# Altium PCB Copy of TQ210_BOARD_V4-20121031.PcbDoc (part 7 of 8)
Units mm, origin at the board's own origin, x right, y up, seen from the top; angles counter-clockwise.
Board outline 191.2 x 131.27 mm, 2 copper layers (TopLayer, BottomLayer); 362 components, 455 nets, 1594 pads, 630 vias.
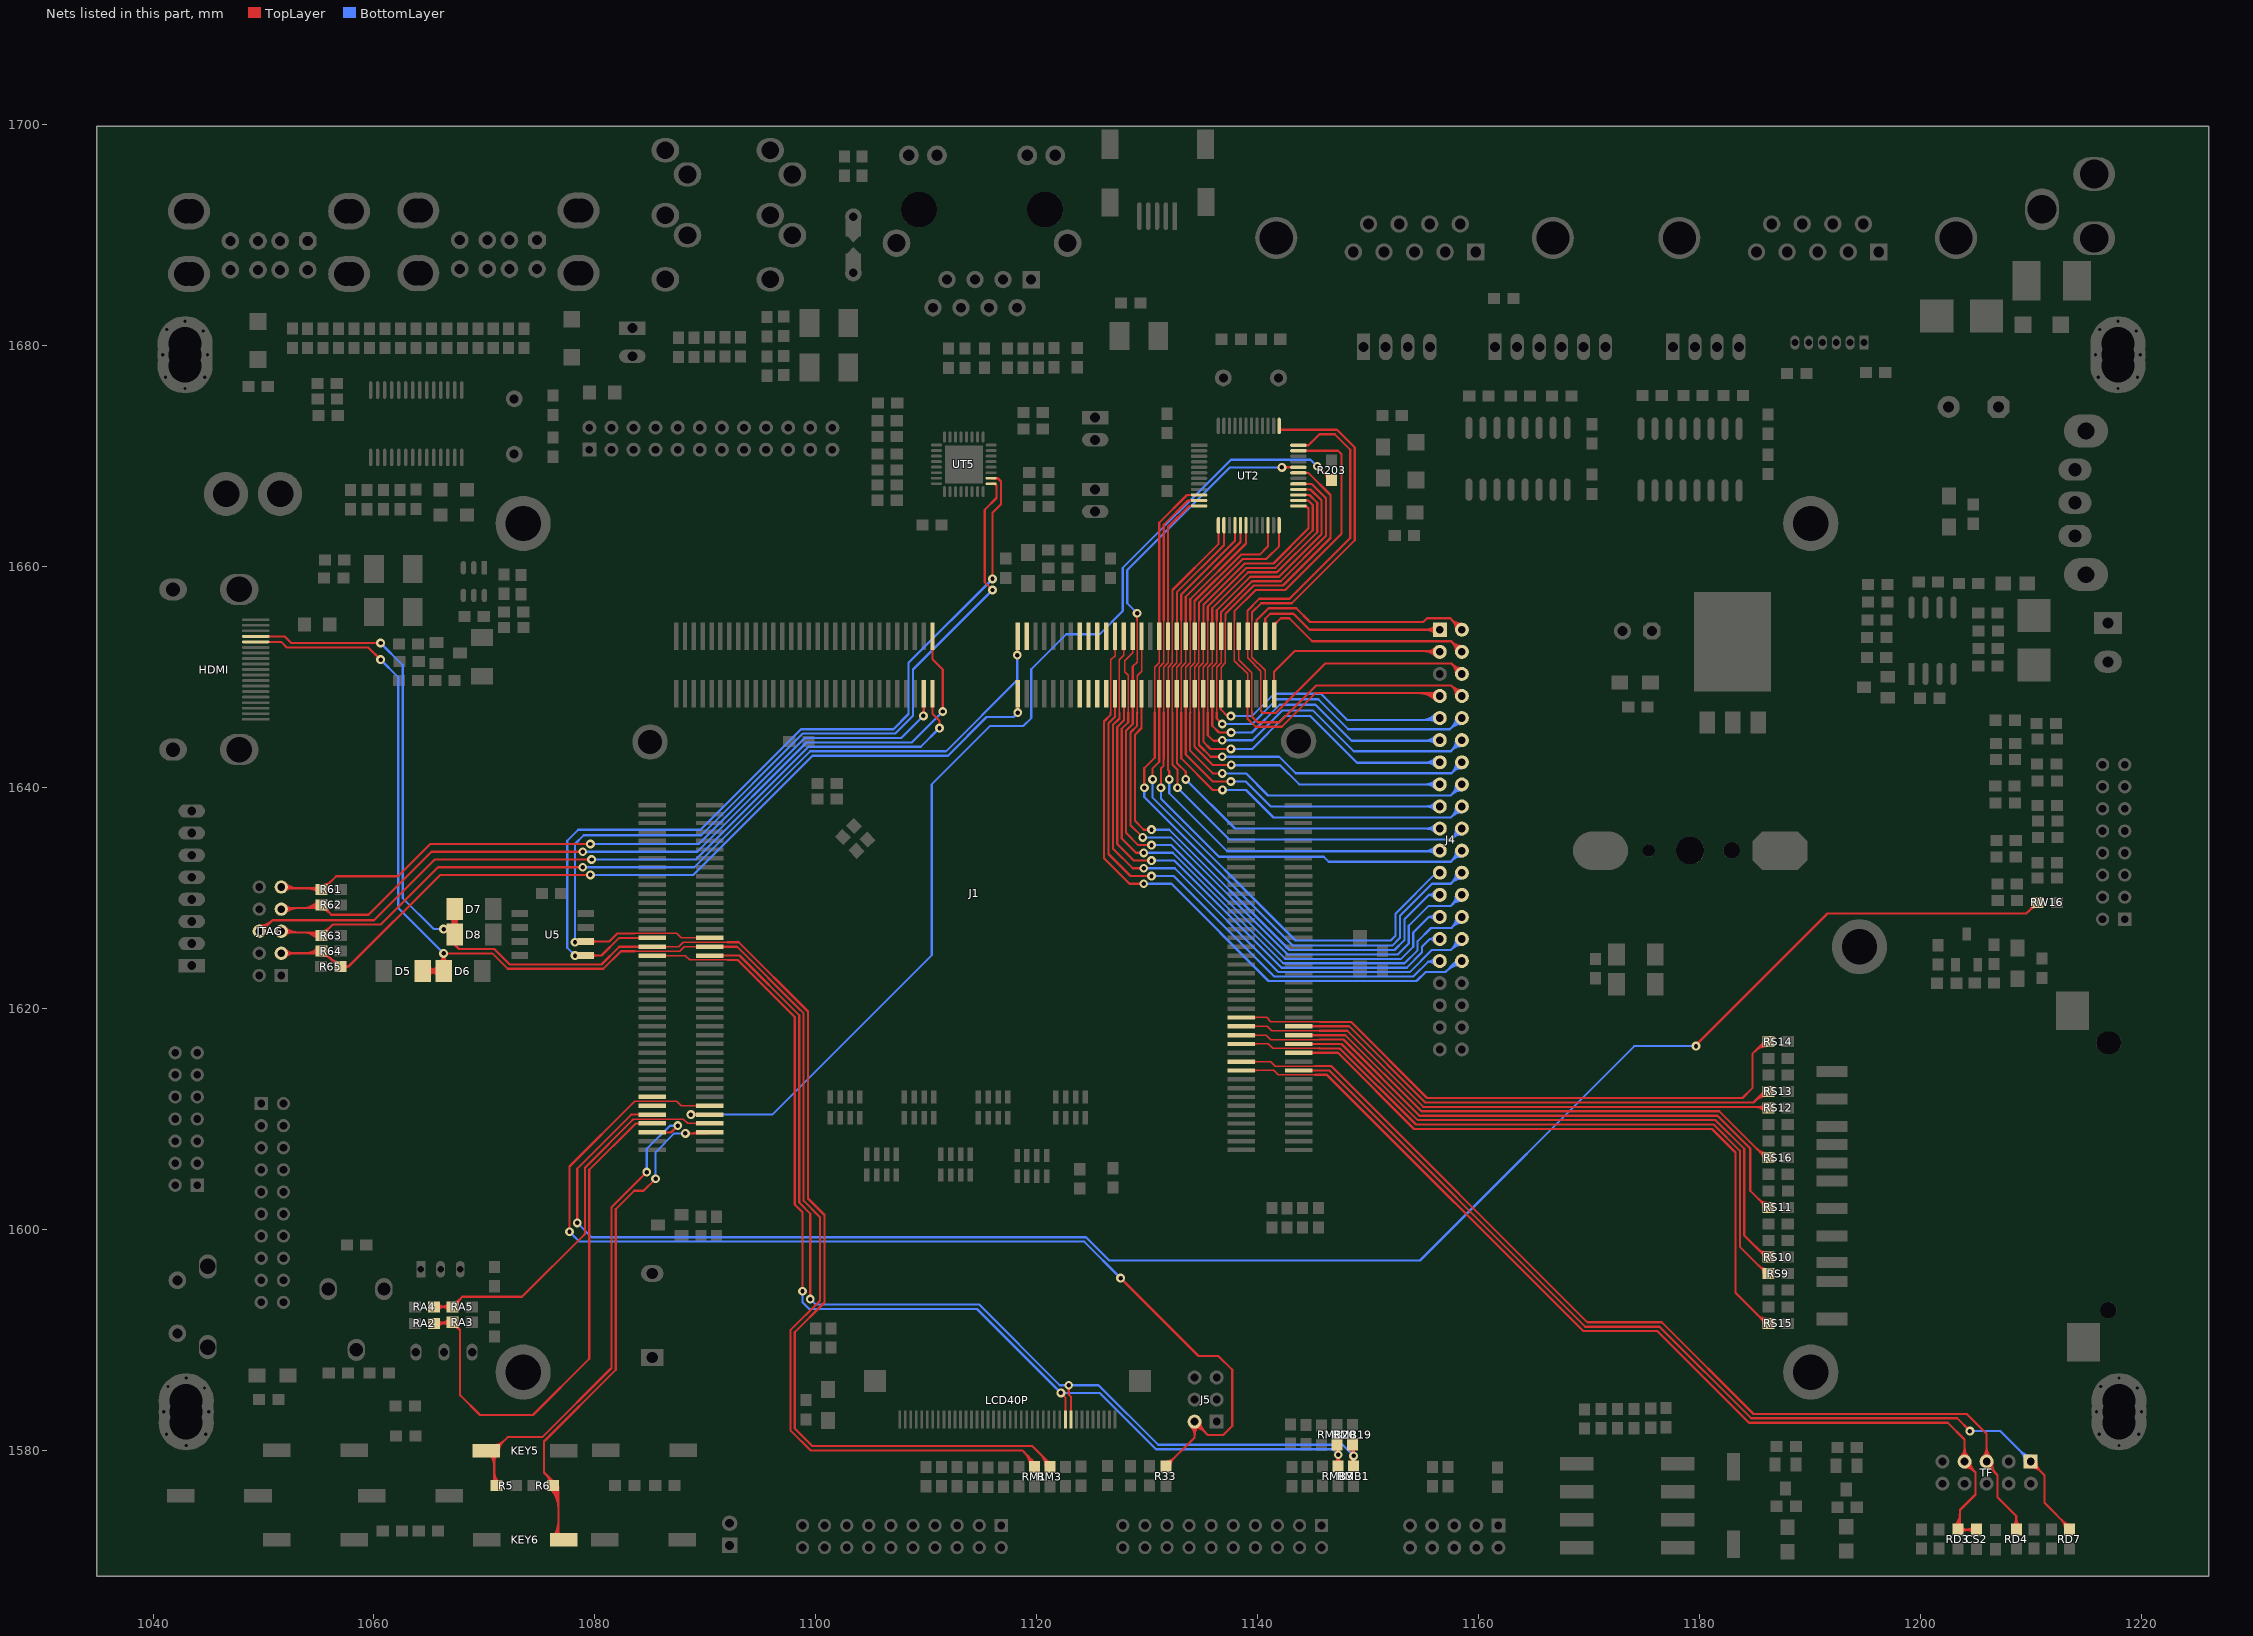
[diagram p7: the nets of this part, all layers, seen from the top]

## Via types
v1: diameter 1, hole 0.5, TopLayer to BottomLayer, 458 vias
v2: diameter 0.8, hole 0.4, TopLayer to BottomLayer, 172 vias

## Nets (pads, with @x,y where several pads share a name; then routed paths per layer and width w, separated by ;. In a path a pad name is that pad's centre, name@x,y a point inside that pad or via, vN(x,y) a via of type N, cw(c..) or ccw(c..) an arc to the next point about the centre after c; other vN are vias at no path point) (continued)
XEINT4: J1.5 KEY5.1 R5.1 | length 52.6
  TopLayer w0.2: KEY5.1@1070.472,1579.622 cw(c1069.44,1578.59) 1070.9,1578.59 ; KEY5.1@1070.614,1579.764 cw(c1069.923,1579.073) 1070.9,1579.073 ; R5.1@1070.767,1577.083 ccw(c1070.446,1577.404) 1070.9,1577.404 ; KEY5.1@1070.826,1580.276 ccw(c1070.826,1581.121) KEY5.1@1071.423,1580.523 ; KEY5.1@1070.826,1580.476 ccw(c1070.826,1581.804) 1071.765,1580.865 ; R5.1@1070.9,1576.8 1070.9,1580 1072.1,1581.2 1075.234,1581.2 1081.5,1587.466 1081.5,1602 v2(1084.7,1605.2) ; 1070.9,1577.645 ccw(c1071.895,1577.645) R5.1@1071.191,1576.941 ; 1070.9,1578.128 ccw(c1072.378,1578.128) R5.1@1071.333,1577.083 ; 1070.9,1578.948 cw(c1071.854,1578.948) KEY5.1@1071.18,1579.622 ; KEY5.1@1071.126,1579.976 cw(c1071.73,1579.976) KEY5.1@1071.303,1580.403 ; KEY5.1@1071.326,1579.976 cw(c1072.412,1579.976) 1071.644,1580.744 ; J1.5@1085.21,1608.79 1086.89,1608.79 v2(1087.5,1609.4) ; J1.5@1086.321,1608.729 cw(c1086.466,1608.584) 1086.466,1608.79 ; J1.5@1086.321,1608.871 ccw(c1086.517,1609.067) 1086.517,1608.79
  BottomLayer w0.2: v2(1084.7,1605.2) 1084.7,1607.3 1086.8,1609.4 v2(1087.5,1609.4)
XEINT5: J1.6 KEY6.1 R6.1 | length 57.5
  TopLayer w0.2: 1075.509,1577.891 cw(c1074.445,1576.826) R6.1@1075.95,1576.803 ; 1075.843,1577.557 cw(c1075.103,1576.816) R6.1@1076.15,1576.8 ; R6.1@1075.967,1576.517 cw(c1074.198,1574.748) 1076.7,1574.748 ; R6.1@1076.109,1576.659 cw(c1074.681,1575.231) 1076.7,1575.231 ; KEY6.1@1076.196,1572.254 ccw(c1074.981,1573.469) 1076.7,1573.469 ; R6.1@1076.25,1576.8 cw(c1075.164,1575.714) 1076.7,1575.714 ; KEY6.1@1076.338,1572.112 ccw(c1075.464,1572.986) 1076.7,1572.986 ; R6.1@1076.391,1576.941 cw(c1075.646,1576.196) 1076.7,1576.196 ; KEY6.1@1076.479,1571.971 ccw(c1075.946,1572.504) 1076.7,1572.504 ; KEY6.1@1076.7,1571.9 1076.7,1576.7 1075.4,1578 1075.4,1580.8 1081.9,1587.3 1081.9,1601.834 1083.566,1603.5 1084.4,1603.5 v2(1085.5,1604.6) ; 1076.7,1572.745 ccw(c1077.395,1572.745) KEY6.1@1076.904,1572.254 ; v2(1088.2,1608.7) 1090.321,1608.7 J1.6@1090.41,1608.79 ; 1088.867,1608.7 ccw(c1088.867,1609.283) J1.6@1089.279,1608.871
  BottomLayer w0.2: v2(1085.5,1604.6) 1085.5,1607 1087.2,1608.7 v2(1088.2,1608.7)
XEINT6: J1.7 RA2.2 RA3.1 | length 52.6
  TopLayer w0.2: RA2.2@1065.45,1591.5 1067.2,1591.5 1067.8,1590.9 1067.8,1585 1069.6,1583.2 1074.406,1583.2 1079.5,1588.294 1079.5,1591.2 1079.5,1605.4 1083.69,1609.59 J1.7@1085.21,1609.59 ; RA2.2@1065.783,1591.217 cw(c1066.466,1590.534) 1066.466,1591.5 cw(c1066.466,1592.466) RA2.2@1065.783,1591.783 ; RA2.2@1065.843,1591.5 ccw(c1065.843,1592.807) RA3.1@1066.767,1591.883 ; RA3.1@1066.767,1591.317 ccw(c1066.326,1590.876) 1066.326,1591.5 ccw(c1066.326,1592.324) RA3.1@1066.909,1591.741 ; RA3.1@1067.15,1591.2 cw(c1067.15,1590.355) 1067.747,1590.953 ; RA3.1@1067.548,1591.56 ccw(c1068.332,1591.482) 1067.775,1590.925
XEINT7: J1.257 RS15.2 | length 62.3
  TopLayer w0.2: J1.257@1143.715,1615.995 1147.276,1615.995 1154.171,1609.1 1181.137,1609.1 1183.269,1606.969 1183.269,1594.259 1186.028,1591.5 RS15.2@1186.25,1591.5 ; 1185.223,1592.305 ccw(c1186.2,1593.282) RS15.2@1186.2,1591.9 ; 1185.564,1591.963 ccw(c1186.2,1592.599) RS15.2@1186.2,1591.7 ; 1185.639,1591.889 cw(c1185.25,1591.5) RS15.2@1185.8,1591.5
XEINT8: J1.8 RA4.2 RA5.1 | length 41
  TopLayer w0.135: 1083.5,1610 1088,1610 1088.4,1609.6 J1.8@1090.4,1609.6 ; J1.8@1089.256,1609.506 ccw(c1089.03,1609.28) 1089.03,1609.6 ccw(c1089.03,1609.92) J1.8@1089.256,1609.694
  TopLayer w0.2: RA4.2@1065.45,1593 RA5.1@1067.1,1593 1068,1593.9 1073.4,1593.9 1079.032,1599.532 ; RA4.2@1065.783,1592.717 cw(c1066.466,1592.034) 1066.466,1593 cw(c1066.466,1593.966) RA4.2@1065.783,1593.283 ; RA5.1@1066.767,1592.717 ccw(c1066.084,1592.034) 1066.084,1593 ccw(c1066.084,1593.966) RA5.1@1066.767,1593.283 ; RA5.1@1067.15,1593.4 ccw(c1067.15,1594.245) 1067.747,1593.647 ; RA5.1@1067.35,1593 cw(c1067.954,1593) RA5.1@1067.527,1593.427 ; RA5.1@1067.55,1593 cw(c1068.636,1593) 1067.868,1593.768 ; 1079.1,1599.6 1079.1,1605.6 1083.426,1609.926
XEINT9: J1.9 RW16.1 | length 162.8
  TopLayer w0.2: v2(1078.4,1600.6) 1078.4,1605.5 1083.3,1610.4 J1.9@1085.2,1610.4 J1.9@1085.21,1610.39 ; v2(1179.7,1616.6) 1179.7,1616.7 1191.6,1628.6 1209.6,1628.6 1210.605,1629.605 RW16.1@1210.621,1629.605 ; 1209.865,1628.865 ccw(c1209.125,1629.605) RW16.1@1210.171,1629.605 ; 1209.946,1628.946 cw(c1210.571,1628.32) RW16.1@1210.571,1629.205 ; RW16.1@1210.206,1629.206 ccw(c1209.808,1629.605) RW16.1@1210.371,1629.605
  BottomLayer w0.2: v2(1078.4,1600.6) 1079.7,1599.3 1124.466,1599.3 1126.566,1597.2 1154.7,1597.2 1174.1,1616.6 v2(1179.7,1616.6)
XEINT10: J1.10 R203.2 | length 101.6
  TopLayer w0.2: v2(1088.7,1610.4) J1.10@1090.4,1610.4 J1.10@1090.41,1610.39 ; J1.10@1089.279,1610.329 ccw(c1089.109,1610.159) 1089.109,1610.4 ccw(c1089.109,1610.641) J1.10@1089.279,1610.471 ; v2(1145.4,1669.1) 1145.45,1669.1 R203.2@1146.7,1667.85 R203.2@1146.5,1667.85 ; 1145.932,1668.618 ccw(c1146.7,1669.386) R203.2@1146.7,1668.3 ; 1146.053,1668.497 cw(c1145.455,1667.9) R203.2@1146.3,1667.9 ; R203.2@1146.273,1668.277 ccw(c1146.7,1668.704) R203.2@1146.7,1668.1
  BottomLayer w0.2: v2(1088.7,1610.4) 1096.059,1610.4 1110.5,1624.84 1110.5,1640.299 1115.798,1645.597 1118.805,1645.597 1119.505,1646.297 1119.505,1650.734 1122.671,1653.9 1125.7,1653.9 1127.8,1656 1127.8,1659.9 1137.6,1669.7 1144.8,1669.7 v2(1145.4,1669.1)
XEINT11: J1.11
XEINT14: J1.12 J5.2 R33.2 | length 113.2
  TopLayer w0.135: 1083.6,1611.6 1087.4,1611.6 1087.8,1611.2 J1.12@1090.4,1611.2 ; J1.12@1089.256,1611.106 ccw(c1089.03,1610.88) 1089.03,1611.2 ccw(c1089.03,1611.52) J1.12@1089.256,1611.294
  TopLayer w0.2: v2(1077.7,1599.8) 1077.7,1605.7 1083.6,1611.6 ; v2(1127.6,1595.6) 1134.652,1588.548 1136.452,1588.548 1137.7,1587.3 1137.7,1582.2 1136.9,1581.4 1135.5,1581.4 J5.2@1134.3,1582.6 1134.3,1581.15 R33.2@1131.7,1578.55 ; R33.2@1131.7,1578.8 ccw(c1131.7,1579.404) R33.2@1132.127,1578.977 ; R33.2@1131.7,1579 ccw(c1131.7,1580.086) 1132.468,1579.318 ; R33.2@1132.1,1578.6 cw(c1132.945,1578.6) 1132.347,1579.197 ; J5.2@1133.922,1582.222 cw(c1133.008,1581.308) 1134.3,1581.308 cw(c1135.592,1581.308) J5.2@1134.678,1582.222 ; J5.2@1134.063,1582.363 cw(c1133.491,1581.791) 1134.3,1581.791 cw(c1135.109,1581.791) J5.2@1134.537,1582.363 ; 1134.872,1582.028 cw(c1135.444,1582.6) 1134.635,1582.6 ccw(c1135.444,1582.6) 1134.872,1582.028 ; 1134.872,1582.028 ccw(c1134.3,1581.456) 1134.3,1582.265 cw(c1134.3,1581.456) 1134.872,1582.028 ; 1135.213,1581.687 cw(c1136.127,1582.6) 1134.835,1582.6 ccw(c1136.127,1582.6) 1135.213,1581.687 ; 1135.213,1581.687 ccw(c1134.3,1580.773) 1134.3,1582.065 cw(c1134.3,1580.773) 1135.213,1581.687
  BottomLayer w0.2: v2(1077.7,1599.8) 1078.6,1598.9 1124.3,1598.9 v2(1127.6,1595.6)
XEINT15: J1.13
XI2CSCL0: J1.50 U5.6 UT5.17 | length 82.7
  TopLayer w0.135: 1083.6,1626.8 1087.4,1626.8 1087.8,1626.4 J1.50@1090.4,1626.4
  TopLayer w0.2: U5.6@1079.194,1626.072 1081.306,1626.072 1082.034,1626.8 1083.6,1626.8 ; U5.6@1079.78,1625.918 cw(c1080.151,1625.547) 1080.151,1626.072 cw(c1080.151,1626.597) U5.6@1079.78,1626.226 ; UT5.17@1115.878,1667.524 1116.176,1667.524 1116.368,1667.332 1116.368,1666.234 1115.3,1665.166 1115.3,1658.6 v2(1116,1657.9) ; UT5.17@1116.235,1667.506 cw(c1115.914,1667.185) 1116.368,1667.185 ; UT5.17@1116.242,1667.502 cw(c1116.144,1667.3) 1116.368,1667.3 ; UT5.17@1116.278,1667.521 ccw(c1116.459,1667.499) 1116.33,1667.37
  BottomLayer w0.2: v2(1078.2,1626) 1078.2,1634.9 1079,1635.7 1089.634,1635.7 1098.834,1644.9 1107.2,1644.9 1108.8,1646.5 1108.8,1650.7 v2(1116,1657.9)
XI2CSCL1: D5.1 D6.2 HDMI.15 J1.48 RM1.2 | length 158.7
  TopLayer w0.12: 1083.6,1625.2 1087.2,1625.2 1087.7,1625.2 1088.09,1625.59 J1.48@1090.41,1625.59
  TopLayer w0.2: HDMI.15@1049.3,1653.2 1051.6,1653.2 1052.1,1652.7 1059.495,1652.7 v2(1060.598,1651.597) ; D5.1@1064.4,1623.4 D6.2@1066.3,1623.4 v2(1066.3,1625) ; D5.1@1064.718,1623.082 cw(c1065.486,1622.314) 1065.486,1623.4 cw(c1065.486,1624.486) D5.1@1064.718,1623.718 ; D5.1@1064.86,1622.94 cw(c1065.969,1621.831) 1065.969,1623.4 cw(c1065.969,1624.969) D5.1@1064.86,1623.86 ; D6.2@1065.84,1622.94 ccw(c1064.731,1621.831) 1064.731,1623.4 ccw(c1064.731,1624.969) D6.2@1065.84,1623.86 ; D6.2@1065.895,1624.158 ccw(c1065.223,1625) v2(1066.3,1625) ; D6.2@1065.982,1623.082 ccw(c1065.214,1622.314) 1065.214,1623.4 ccw(c1065.214,1624.486) D6.2@1065.982,1623.718 ; D6.2@1066.019,1624.002 ccw(c1065.555,1624.585) 1066.3,1624.585 ccw(c1067.045,1624.585) D6.2@1066.581,1624.002 ; D6.2@1066.705,1624.158 cw(c1067.377,1625) v2(1066.3,1625) ; 1083.6,1625.2 1082.367,1625.2 1080.767,1623.6 1072.1,1623.6 1070.7,1625 v2(1066.3,1625) ; J1.48@1090.41,1625.59 1092.879,1625.59 1098.4,1620.068 1098.9,1619.569 1098.9,1602.6 1100.39,1601.11 1100.39,1593.556 1097.7,1590.866 1097.7,1581.82 1099.52,1580 1118.7,1580 RM1.2@1120,1578.7 ; 1118.868,1579.832 cw(c1117.585,1578.548) RM1.2@1119.4,1578.548 ; 1119.21,1579.49 cw(c1118.268,1578.548) RM1.2@1119.6,1578.548 ; 1119.551,1579.149 cw(c1118.951,1578.548) RM1.2@1119.8,1578.548
  BottomLayer w0.2: v2(1060.598,1651.597) 1062.2,1649.995 1062.2,1629.1 v2(1066.3,1625)
XI2CSCL2: J1.46 LCD40P.32 RMB1.2 RMB19.2 | length 100.1
  TopLayer w0.2: J1.46@1090.41,1624.79 1090.421,1624.8 1093.103,1624.8 1098.5,1619.403 1098.5,1602.434 1099.5,1601.434 v2(1099.5,1593.7) ; v2(1122.9,1585.9) 1122.9,1585.066 1123.1,1584.866 LCD40P.32@1123.1,1582.8 ; RMB19.2@1148.317,1580.217 cw(c1147.393,1579.293) v2@1148.7,1579.293 ; RMB1.2@1148.417,1578.883 ccw(c1147.734,1579.566) 1148.7,1579.566 ccw(c1149.666,1579.566) RMB1.2@1148.983,1578.883 ; RMB19.2@1148.459,1580.359 cw(c1147.876,1579.776) 1148.7,1579.776 cw(c1149.324,1579.776) RMB19.2@1148.883,1580.217 ; RMB1.2@1148.7,1578.55 RMB19.2@1148.7,1580.25
  BottomLayer w0.2: v2(1099.5,1593.7) 1100,1593.2 1114.8,1593.2 1122.1,1585.9 1125.6,1585.9 1131,1580.5 1147.7,1580.5 v2(1148.7,1579.5)
XI2CSDA0: J1.49 U5.5 UT5.18 | length 80.2
  TopLayer w0.2: U5.5@1079.194,1624.802 1080.602,1624.802 1082.2,1626.4 J1.49@1085.2,1626.4 ; U5.5@1079.78,1624.648 cw(c1080.151,1624.277) 1080.151,1624.802 cw(c1080.151,1625.327) U5.5@1079.78,1624.956 ; UT5.18@1115.878,1668.024 1116.471,1668.024 1116.768,1667.726 1116.768,1665.668 1116,1664.9 v2(1116,1658.9) ; UT5.18@1116.253,1667.999 cw(c1116.253,1667.413) 1116.667,1667.827 ; UT5.18@1116.259,1668 cw(c1116.347,1667.682) 1116.579,1667.915
  BottomLayer w0.2: v2(1078.2,1624.8) 1077.5,1625.5 1077.5,1635.2 1078.5,1636.2 1089.569,1636.2 1098.669,1645.3 1107.034,1645.3 1108.4,1646.666 1108.4,1651.3 v2(1116,1658.9)
XI2CSDA1: D7.1 D8.2 HDMI.16 J1.47 RM3.2 | length 154.9
  TopLayer w0.135: J1.47@1085.2,1625.6 1087.6,1625.6 1088,1626 1092,1626
  TopLayer w0.2: HDMI.16@1049.3,1653.7 1051.9,1653.7 1052.503,1653.097 v2(1060.598,1653.097) ; D8.2@1066.84,1627.41 ccw(c1065.731,1628.519) 1067.3,1628.519 ccw(c1068.869,1628.519) D8.2@1067.76,1627.41 ; D7.1@1066.84,1628.29 cw(c1065.731,1627.181) 1067.3,1627.181 cw(c1068.869,1627.181) D7.1@1067.76,1628.29 ; D8.2@1066.982,1627.268 ccw(c1066.214,1628.036) 1067.3,1628.036 ccw(c1068.386,1628.036) D8.2@1067.618,1627.268 ; D7.1@1066.982,1628.432 cw(c1066.214,1627.664) 1067.3,1627.664 cw(c1068.386,1627.664) D7.1@1067.618,1628.432 ; D7.1@1067.3,1629.4 1067.3,1625.8 1067.7,1625.4 1070.9,1625.4 1072.3,1624 1080.601,1624 1082.201,1625.6 J1.47@1085.2,1625.6 J1.47@1085.21,1625.59 ; 1092,1626 1093.034,1626 1099.3,1619.734 1099.3,1602.8 1100.79,1601.31 1100.79,1593.39 1098.1,1590.7 1098.1,1581.985 1099.685,1580.4 1119.6,1580.4 RM3.2@1121.3,1578.7 ; 1120.339,1579.661 cw(c1119.226,1578.548) RM3.2@1120.8,1578.548 ; 1120.681,1579.319 cw(c1119.909,1578.548) RM3.2@1121,1578.548 ; 1120.947,1579.053 ccw(c1121.2,1579.306) RM3.2@1121.2,1578.948
  BottomLayer w0.2: v2(1060.598,1653.097) 1062.6,1651.095 1062.6,1630 1065.4,1627.2 v2(1066.3,1627.2)
XI2CSDA2: J1.45 LCD40P.31 RMB3.2 RMB20.2 | length 103.5
  TopLayer w0.135: J1.45@1085.2,1624.8 1088.2,1624.8 1088.6,1624.4 1092,1624.4
  TopLayer w0.2: 1092,1624.4 1092.937,1624.4 1098.1,1619.237 1098.1,1602.269 1098.8,1601.569 v2(1098.8,1594.4) ; v2(1122.2,1585.2) 1122.6,1584.8 LCD40P.31@1122.6,1582.8 ; RMB20.2@1146.917,1580.217 cw(c1145.993,1579.293) v2@1147.3,1579.293 ; RMB3.2@1147.017,1578.883 ccw(c1146.334,1579.566) 1147.3,1579.566 ccw(c1148.266,1579.566) RMB3.2@1147.583,1578.883 ; RMB20.2@1147.059,1580.359 cw(c1146.476,1579.776) 1147.3,1579.776 cw(c1147.924,1579.776) RMB20.2@1147.483,1580.217 ; RMB3.2@1147.3,1578.55 RMB20.2@1147.3,1580.25
  BottomLayer w0.2: v2(1098.8,1594.4) 1098.8,1593.4 1099.4,1592.8 1114.6,1592.8 v2(1122.2,1585.2) 1125.7,1585.2 1130.8,1580.1 1146.8,1580.1 v2(1147.3,1579.6)
XJDBGSEL: J1.143
XJTCK: J1.138 JTAG.9 R61.2 | length 73.9
  TopLayer w0.2: JTAG.9@1051.712,1630.904 1055.504,1630.904 1056.585,1631.985 1062.185,1631.985 1065.1,1634.9 v2(1079.6,1634.9) ; JTAG.9@1051.824,1631.216 ccw(c1052.578,1631.969) 1052.578,1630.904 ccw(c1052.578,1630.038) JTAG.9@1051.966,1630.65 ; JTAG.9@1051.966,1631.357 ccw(c1053.061,1632.452) 1053.061,1630.904 ; 1053.968,1630.904 cw(c1053.968,1629.577) R61.2@1054.906,1630.515 ; 1054.451,1630.904 cw(c1054.451,1630.06) R61.2@1055.048,1630.656 ; 1054.479,1630.904 ccw(c1054.479,1631.508) R61.2@1054.906,1631.081 ; R61.2@1055.289,1630.998 ccw(c1055.289,1631.743) 1055.816,1631.216 ; R61.2@1055.289,1631.198 ccw(c1055.289,1632.426) 1056.158,1631.558 ; R61.2@1055.689,1630.798 cw(c1056.392,1630.798) 1055.895,1631.295 ; J1.138@1109.7,1647.385 cw(c1109.529,1647.214) 1109.771,1647.214 cw(c1110.012,1647.214) J1.138@1109.841,1647.385 ; v2@1109.771,1646.521 J1.138@1109.771,1648.506
  BottomLayer w0.2: v2(1079.6,1634.9) 1089.4,1634.9 1099,1644.5 1107.75,1644.5 v2(1109.75,1646.5)
XJTDI: J1.141 JTAG.5 R63.2 | length 88.8
  TopLayer w0.2: JTAG.5@1051.712,1626.904 1051.716,1626.9 R63.2@1055.3,1626.9 ; JTAG.5@1051.824,1627.216 ccw(c1052.586,1627.978) 1052.586,1626.9 ; JTAG.5@1051.966,1626.65 cw(c1052.569,1626.047) 1052.569,1626.9 ; JTAG.5@1051.966,1627.357 ccw(c1053.069,1628.461) 1053.069,1626.9 ; 1053.494,1626.9 cw(c1053.494,1624.903) R63.2@1054.906,1626.315 ; 1053.977,1626.9 cw(c1053.977,1625.386) R63.2@1055.048,1626.456 ; 1054.46,1626.9 cw(c1054.46,1625.869) R63.2@1055.189,1626.598 ; R63.2@1055.239,1626.598 1056.241,1627.6 1060.6,1627.6 1065.8,1632.8 v2(1078.9,1632.8) ; R63.2@1055.289,1626.998 ccw(c1055.289,1627.843) 1055.887,1627.245 ; R63.2@1055.489,1626.598 cw(c1056.093,1626.598) R63.2@1055.666,1627.025 ; R63.2@1055.689,1626.598 cw(c1056.776,1626.598) 1056.007,1627.366 ; v2(1118.25,1652) J1.141@1118.25,1653.5 ; v2@1118.25,1652.304 cw(c1118.647,1652.304) J1.141@1118.366,1652.585 ; J1.141@1118.296,1653.5 J1.141@1118.296,1653.706
  BottomLayer w0.2: v2(1078.9,1632.8) 1089.001,1632.8 1099.501,1643.3 1111.804,1643.3 1118.25,1649.746 v2(1118.25,1652)
XJTDO: J1.140 JTAG.6 | length 75.7
  TopLayer w0.2: JTAG.6@1049.612,1627.304 ccw(c1049.612,1628.511) 1050.466,1627.657 ; JTAG.6@1049.612,1627.504 ccw(c1049.612,1629.194) 1050.807,1627.999 ; JTAG.6@1049.712,1626.904 1050.808,1628 1060,1628 1065.5,1633.5 v2(1079.7,1633.5) ; JTAG.6@1050.112,1627.004 cw(c1050.836,1627.004) 1050.324,1627.516 ; J1.140@1110.5,1647.385 cw(c1110.329,1647.214) 1110.571,1647.214 cw(c1110.812,1647.214) J1.140@1110.641,1647.385 ; J1.140@1110.571,1648.506 1110.571,1646.7 1111.2,1646.071 v2(1111.2,1645.4)
  BottomLayer w0.2: v2(1079.7,1633.5) 1089.135,1633.5 1099.335,1643.7 1109.5,1643.7 v2(1111.2,1645.4)
XJTMS: J1.139 JTAG.7 R62.2 | length 83.8
  TopLayer w0.2: JTAG.7@1051.6,1629.1 1054.941,1629.1 R62.2@1055.239,1629.398 1056.137,1628.5 1059.5,1628.5 1065.2,1634.2 v2(1078.9,1634.2) ; JTAG.7@1051.824,1628.791 cw(c1052.569,1628.047) 1052.569,1629.1 ; JTAG.7@1051.966,1628.65 cw(c1053.052,1627.564) 1053.052,1629.1 ; JTAG.7@1051.966,1629.357 ccw(c1052.586,1629.978) 1052.586,1629.1 ; 1053.504,1629.1 ccw(c1053.504,1631.083) R62.2@1054.906,1629.681 ; 1053.987,1629.1 ccw(c1053.987,1630.6) R62.2@1055.048,1629.539 ; 1054.47,1629.1 ccw(c1054.47,1630.117) R62.2@1055.189,1629.398 ; R62.2@1055.289,1628.998 cw(c1055.289,1628.153) 1055.887,1628.75 ; R62.2@1055.489,1629.398 ccw(c1056.093,1629.398) R62.2@1055.666,1628.971 ; R62.2@1055.689,1629.398 ccw(c1056.776,1629.398) 1056.007,1628.63 ; J1.139@1110.5,1652.585 cw(c1110.329,1652.414) 1110.571,1652.414 cw(c1110.812,1652.414) J1.139@1110.641,1652.585 ; J1.139@1110.571,1653.706 1110.571,1651.629 1111.5,1650.699 v2(1111.5,1646.9)
  BottomLayer w0.2: v2(1078.9,1634.2) 1089.27,1634.2 1099.17,1644.1 1108.7,1644.1 v2(1111.5,1646.9)
XJTRSTN: J1.142 JTAG.3 R64.2 R65.2 | length 89.4
  TopLayer w0.2: JTAG.3@1051.612,1625.004 1055.596,1625.004 R65.2@1056.6,1624 ; JTAG.3@1051.824,1624.791 cw(c1052.336,1624.279) 1052.336,1625.004 cw(c1052.336,1625.728) JTAG.3@1051.824,1625.216 ; JTAG.3@1051.966,1624.65 cw(c1052.819,1623.796) 1052.819,1625.004 cw(c1052.819,1626.211) JTAG.3@1051.966,1625.357 ; 1053.754,1625.004 ccw(c1053.754,1626.633) R64.2@1054.906,1625.481 ; 1054.237,1625.004 ccw(c1054.237,1626.15) R64.2@1055.048,1625.339 ; R64.2@1054.692,1625.004 cw(c1054.692,1624.701) R64.2@1054.906,1624.915 ; R64.2@1054.72,1625.004 ccw(c1054.72,1625.667) R64.2@1055.189,1625.198 ; R64.2@1055.289,1624.798 cw(c1055.289,1623.559) 1056.165,1624.435 ; R64.2@1055.289,1624.998 cw(c1055.289,1624.242) 1055.823,1624.777 ; R64.2@1055.689,1625.198 ccw(c1056.382,1625.198) 1055.892,1624.708 ; 1056.035,1624.565 ccw(c1056.911,1625.441) R65.2@1056.911,1624.202 ; 1056.308,1624.292 cw(c1055.818,1623.802) R65.2@1056.511,1623.802 ; 1056.377,1624.223 ccw(c1056.911,1624.758) R65.2@1056.911,1624.002 ; R65.2@1056.961,1623.802 1057.702,1623.802 ; R65.2@1057.358,1623.603 cw(c1057.702,1623.405) 1057.702,1623.802 ; R65.2@1057.358,1624.001 ccw(c1057.702,1624.199) 1057.702,1623.802 ; v2(1079.6,1632.1) 1066,1632.1 1057.702,1623.802 ; J1.142@1118.225,1647.385 cw(c1118.054,1647.214) 1118.296,1647.214 cw(c1118.537,1647.214) J1.142@1118.366,1647.385 ; v2(1118.296,1646.796) J1.142@1118.296,1648.506
  BottomLayer w0.2: v2(1079.6,1632.1) 1088.901,1632.1 1099.701,1642.9 1111.97,1642.9 1115.466,1646.397 1117.897,1646.397 v2(1118.296,1646.796)
XM0ADDR0: J1.170 J4.25 | length 48.6
  TopLayer w0.2: J1.170@1129.496,1648.506 1129.496,1645.396 1128.9,1644.8 1128.9,1637 1129.7,1636.2 v2(1130.4,1636.2)
  BottomLayer w0.2: v2(1130.4,1636.2) 1132,1636.2 1142.9,1625.3 1152.4,1625.3 1153.294,1626.194 1153.294,1628.07 1155.523,1630.3 ; J4.25@1156.049,1630.012 ccw(c1155.523,1629.676) 1155.523,1630.3 ; J4.25@1156.049,1630.588 cw(c1155.523,1630.924) 1155.523,1630.3 ; J4.25@1156.5,1630.3 1155.523,1630.3
XM0ADDR1: J1.169 J4.26 | length 58.8
  TopLayer w0.135: 1129.094,1646.797 1129.094,1650.14 1129.496,1650.541 J1.169@1129.496,1653.706
  TopLayer w0.2: 1129.1,1646.8 1129.096,1646.796 1129.096,1645.6 1128.5,1645.004 1128.5,1636.6 v2(1129.6,1635.5)
  BottomLayer w0.2: v2(1129.6,1635.5) 1132.134,1635.5 1142.734,1624.9 1152.7,1624.9 1153.694,1625.894 1153.694,1627.494 1155.5,1629.3 1157.5,1629.3 J4.26@1158.5,1630.3 ; J4.26@1157.965,1630.3 cw(c1156.673,1630.3) 1157.587,1629.387 cw(c1158.5,1628.473) J4.26@1158.5,1629.765 ; J4.26@1158.165,1630.3 cw(c1157.356,1630.3) 1157.928,1629.728 cw(c1158.5,1629.156) J4.26@1158.5,1629.965
XM0ADDR2: J1.168 J4.27 UT2.32 | length 80.6
  TopLayer w0.135: 1128.696,1650.979 1129.095,1651.378 1129.095,1655.205
  TopLayer w0.2: 1128.696,1650.979 1128.696,1645.767 1128.1,1645.172 1128.1,1635.9 1129.2,1634.8 v2(1130.4,1634.8) ; 1129.095,1655.205 v2@1129.095,1655.695 ; v2(1142.2,1669) 1142.204,1669.004 UT2.32@1143.703,1669.004
  BottomLayer w0.2: v2(1129.1,1655.8) 1128.2,1656.7 1128.2,1659.7 1137.5,1669 v2(1142.2,1669) ; v2(1130.4,1634.8) 1132.2,1634.8 1142.5,1624.5 1153,1624.5 1154.094,1625.594 1154.094,1626.894 1155.5,1628.3 ; J4.27@1156.055,1628.003 ccw(c1155.5,1627.633) 1155.5,1628.3 ; J4.27@1156.055,1628.597 cw(c1155.5,1628.967) 1155.5,1628.3 ; J4.27@1156.5,1628.3 1155.5,1628.3
XM0ADDR3: J1.167 J4.28 | length 59.9
  TopLayer w0.135: 1128.296,1646.804 1128.296,1650.185 1127.963,1650.517 1127.963,1651.492 1128.696,1652.224 J1.167@1128.696,1653.706
  TopLayer w0.2: 1128.296,1645.933 1127.7,1645.337 1127.7,1635.4 1129,1634.1 v2(1129.7,1634.1) ; 1128.3,1645.933 1128.3,1646.8
  BottomLayer w0.2: v2(1129.7,1634.1) 1132.334,1634.1 1142.334,1624.1 1153.3,1624.1 1154.494,1625.294 1154.494,1626.094 1155.7,1627.3 1157.55,1627.3 J4.28@1158.5,1628.25 ; 1157.575,1627.325 ccw(c1156.633,1628.267) J4.28@1157.965,1628.291 ; 1157.672,1627.422 cw(c1158.5,1626.594) J4.28@1158.5,1627.765 ; 1157.908,1627.658 ccw(c1157.288,1628.279) J4.28@1158.165,1628.294 ; 1158.013,1627.763 cw(c1158.5,1627.277) J4.28@1158.5,1627.965
XM0ADDR4: J1.166 J4.29 | length 50.1
  TopLayer w0.2: J1.166@1127.906,1648.495 1127.906,1646.109 1127.3,1645.503 1127.3,1634.9 1128.8,1633.4 v2(1130.4,1633.4)
  BottomLayer w0.2: v2(1130.4,1633.4) 1132.469,1633.4 1142.169,1623.7 1153.5,1623.7 1154.894,1625.094 1154.894,1625.595 1155.598,1626.3 ; J4.29@1156.03,1626.044 ccw(c1155.598,1625.808) 1155.598,1626.3 ; J4.29@1156.03,1626.556 cw(c1155.598,1626.792) 1155.598,1626.3 ; J4.29@1156.5,1626.3 1155.598,1626.3
XM0ADDR5: J1.165 J4.30 | length 60.9
  TopLayer w0.135: 1127.497,1646.803 1127.497,1651.592 1127.896,1651.991 J1.165@1127.896,1653.706 ; J1.165@1127.802,1652.562 cw(c1127.576,1652.336) 1127.896,1652.336 cw(c1128.215,1652.336) J1.165@1127.989,1652.562
  TopLayer w0.2: 1127.496,1646.264 1126.9,1645.669 1126.9,1634.5 1128.7,1632.7 v2(1129.7,1632.7) ; 1127.5,1646.264 1127.5,1646.8
  BottomLayer w0.2: v2(1129.7,1632.7) 1132.5,1632.7 1141.9,1623.3 1153.778,1623.3 1155.778,1625.3 1157.5,1625.3 J4.30@1158.5,1626.3 ; J4.30@1157.965,1626.3 cw(c1156.673,1626.3) 1157.587,1625.387 cw(c1158.5,1624.473) J4.30@1158.5,1625.765 ; J4.30@1158.165,1626.3 cw(c1157.356,1626.3) 1157.928,1625.728 cw(c1158.5,1625.156) J4.30@1158.5,1625.965
XM0ADDR6: J1.164 J4.31 | length 51.8
  TopLayer w0.2: J1.164@1127.096,1648.506 1127.096,1646.43 1126.5,1645.834 1126.5,1634 1128.5,1632 v2(1130.4,1632)
  BottomLayer w0.2: v2(1130.4,1632) 1132.4,1632 1141.027,1623.373 1141.5,1622.9 1154.1,1622.9 1155.45,1624.25 ; 1155.809,1624.25 ccw(c1155.809,1624.728) J4.31@1156.215,1624.476 ; J4.31@1156.045,1624.582 cw(c1155.45,1624.95) 1155.45,1624.25 ; J4.31@1156.093,1623.953 ccw(c1155.45,1623.406) 1155.45,1624.25 ; J4.31@1156.5,1624.25 1155.45,1624.25
XM0ADDR7: J1.163 J4.32 | length 62.3
  TopLayer w0.135: 1126.695,1646.796 1126.695,1651.565 1127.096,1651.965 J1.163@1127.096,1653.706 ; J1.163@1127.002,1652.562 cw(c1126.776,1652.336) 1127.096,1652.336 cw(c1127.415,1652.336) J1.163@1127.189,1652.562
  TopLayer w0.2: 1126.696,1646.796 1126.696,1646.596 1126.1,1646 1126.1,1633.6 1128.4,1631.3 v2(1129.7,1631.3)
  BottomLayer w0.2: v2(1129.7,1631.3) 1132.2,1631.3 1141,1622.5 1154.4,1622.5 1155.2,1623.3 1157,1623.3 1158,1624.3 J4.32@1158.5,1624.3 ; 1157.088,1623.388 cw(c1158.482,1621.994) J4.32@1158.497,1623.965 ; 1157.425,1623.725 cw(c1158.487,1622.664) J4.32@1158.499,1624.165 ; 1157.763,1624.063 cw(c1158.492,1623.333) J4.32@1158.501,1624.365
XM0ADDR8: J1.162
XM0ADDR9: J1.161
XM0ADDR10: J1.160
XM0ADDR11: J1.159
XM0ADDR12: J1.158
XM0ADDR13: J1.157
XM0ADDR14: J1.156
XM0ADDR15: J1.155
XM0BE0: J1.189
XM0BE1: J1.190
XM0CSN0: J1.195 J4.2 | length 25
  TopLayer w0.2: J1.195@1139.896,1653.706 J1.195@1139.952,1653.762 ; J1.195@1139.9,1653.71 1139.9,1655.164 1140.986,1656.25 1143.5,1656.25 1144.75,1655 1155,1655 1155.35,1655.35 1157.45,1655.35 J4.2@1158.5,1654.3 ; J4.2@1157.965,1654.3 ccw(c1156.673,1654.3) 1157.587,1655.213 ccw(c1158.5,1656.127) J4.2@1158.5,1654.835 ; J4.2@1158.165,1654.3 ccw(c1157.356,1654.3) 1157.928,1654.872 ccw(c1158.5,1655.444) J4.2@1158.5,1654.635
XM0CSN1: J1.198 UT2.37 | length 35.8
  TopLayer w0.12: J1.198@1140.696,1648.506 J1.198@1140.696,1648.508
  TopLayer w0.135: 1139.497,1655.197 1139.497,1651.817 1140.696,1650.619 J1.198@1140.696,1648.506
  TopLayer w0.2: 1139.5,1655.2 1139.5,1655.877 ; 1139.54,1655.917 1140.323,1656.7 1143.1,1656.7 1148.8,1662.4 1148.8,1670.8 1147.2,1672.4 UT2.37@1141.903,1672.4
XM0CSN3: J1.197 J4.1 | length 21.9
  TopLayer w0.2: J1.197@1140.625,1654.827 ccw(c1140.454,1654.997) 1140.696,1654.997 ccw(c1140.937,1654.997) J1.197@1140.766,1654.827 ; J1.197@1140.696,1653.706 1140.696,1655.293 1141.153,1655.75 1143.25,1655.75 1144.7,1654.3 J4.1@1156.5,1654.3 ; J4.1@1156.122,1653.922 ccw(c1155.208,1653.008) 1155.208,1654.3 ccw(c1155.208,1655.592) J4.1@1156.122,1654.678 ; J4.1@1156.263,1654.063 ccw(c1155.691,1653.491) 1155.691,1654.3 ccw(c1155.691,1655.109) J4.1@1156.263,1654.537
XM0CSN4: J1.200 J4.3 | length 21.5
  TopLayer w0.2: J1.200@1141.425,1649.627 ccw(c1141.254,1649.797) 1141.496,1649.797 ccw(c1141.737,1649.797) J1.200@1141.566,1649.627 ; J1.200@1141.496,1648.506 1141.496,1650.5 1143.367,1652.372 1156.428,1652.372 J4.3@1156.5,1652.3 ; 1155.036,1652.372 cw(c1155.036,1650.836) J4.3@1156.122,1651.922 ; 1155.381,1652.372 ccw(c1155.381,1653.419) J4.3@1156.122,1652.678 ; 1155.518,1652.372 cw(c1155.518,1651.318) J4.3@1156.263,1652.063 ; 1155.864,1652.372 ccw(c1155.864,1652.936) J4.3@1156.263,1652.537
XM0CSN5: J1.199 J4.4 | length 23.1
  TopLayer w0.2: J1.199@1141.496,1653.706 1141.496,1654.728 1142.111,1655.343 1142.873,1655.343 1144.956,1653.261 1157.539,1653.261 J4.4@1158.5,1652.3 ; J1.199@1141.496,1654.856 ccw(c1141.496,1655.164) 1141.714,1654.946 ; J4.4@1157.965,1652.3 ccw(c1156.673,1652.3) 1157.587,1653.213 ccw(c1158.5,1654.127) J4.4@1158.5,1652.835 ; J4.4@1158.165,1652.3 ccw(c1157.356,1652.3) 1157.928,1652.872 ccw(c1158.5,1653.444) J4.4@1158.5,1652.635
XM0DATA0: J1.180 J4.17 UT2.18 | length 51.3
  TopLayer w0.135: J1.180@1133.496,1648.506 1133.496,1650.896 1133.896,1651.296 1133.896,1655.196
  TopLayer w0.2: J1.180@1133.496,1648.506 1133.496,1643.004 1135.939,1640.561 v2(1137.59,1640.561) ; 1133.9,1655.2 1133.9,1657.06 1138.953,1662.113 UT2.18@1138.953,1663.754
  BottomLayer w0.2: v2(1137.59,1640.561) 1138.939,1640.561 1141.2,1638.3 J4.17@1156.5,1638.3 ; J4.17@1156.122,1637.922 ccw(c1155.208,1637.008) 1155.208,1638.3 ccw(c1155.208,1639.592) J4.17@1156.122,1638.678 ; J4.17@1156.263,1638.063 ccw(c1155.691,1637.491) 1155.691,1638.3 ccw(c1155.691,1639.109) J4.17@1156.263,1638.537
XM0DATA1: J1.179 J4.18 UT2.17 | length 54.6
  TopLayer w0.135: 1133.094,1646.797 1133.094,1650.894 1133.496,1651.296 J1.179@1133.496,1653.706
  TopLayer w0.2: 1133.1,1646.8 1133.096,1646.796 1133.096,1642.654 1135.951,1639.799 v2(1136.828,1639.799) ; J1.179@1133.496,1653.706 1133.5,1653.71 1133.5,1657.3 1138.453,1662.253 UT2.17@1138.453,1663.754
  BottomLayer w0.2: v2(1136.828,1639.799) 1138.951,1639.799 1141.45,1637.3 1157.5,1637.3 J4.18@1158.431,1638.231 ; J4.18@1157.965,1638.3 cw(c1156.673,1638.3) 1157.587,1637.387 cw(c1158.5,1636.473) J4.18@1158.5,1637.765 ; J4.18@1158.165,1638.3 cw(c1157.356,1638.3) 1157.928,1637.728 cw(c1158.5,1637.156) J4.18@1158.5,1637.965
XM0DATA2: J1.178 J4.19 UT2.16 | length 53.6
  TopLayer w0.135: J1.178@1132.696,1648.506 1132.696,1650.896 1133.094,1651.294 1133.094,1655.194
  TopLayer w0.2: J1.178@1132.696,1648.506 1132.696,1642.241 1133.5,1641.436 v2(1133.5,1640.75) ; 1133.1,1655.2 1133.1,1657.5 1137.953,1662.353 UT2.16@1137.953,1663.754
  BottomLayer w0.2: v2(1133.5,1640.75) 1137.95,1636.3 J4.19@1156.5,1636.3 ; J4.19@1156.122,1635.922 ccw(c1155.208,1635.008) 1155.208,1636.3 ccw(c1155.208,1637.592) J4.19@1156.122,1636.678 ; J4.19@1156.263,1636.063 ccw(c1155.691,1635.491) 1155.691,1636.3 ccw(c1155.691,1637.109) J4.19@1156.263,1636.537
XM0DATA3: J1.177 J4.20 UT2.14 | length 57.3
  TopLayer w0.135: 1132.296,1646.804 1132.296,1650.896 1132.696,1651.296 J1.177@1132.696,1653.706
  TopLayer w0.2: 1132.3,1646.8 1132.3,1642.071 1132.75,1641.621 v2(1132.75,1640) ; J1.177@1132.696,1653.706 1132.696,1657.696 1136.953,1661.953 UT2.14@1136.953,1663.754
  BottomLayer w0.2: v2(1132.75,1640) 1137.45,1635.3 1157.5,1635.3 1158.4,1636.2 J4.20@1158.5,1636.3 ; J4.20@1157.965,1636.3 cw(c1156.673,1636.3) 1157.587,1635.387 cw(c1158.5,1634.473) J4.20@1158.5,1635.765 ; J4.20@1158.165,1636.3 cw(c1157.356,1636.3) 1157.928,1635.728 cw(c1158.5,1635.156) J4.20@1158.5,1635.965
XM0DATA4: J1.176 J4.21 UT2.13 | length 56.2
  TopLayer w0.135: J1.176@1131.896,1648.506 1131.896,1650.897 1132.296,1651.297 1132.296,1655.196
  TopLayer w0.2: J1.176@1131.896,1648.506 1131.896,1641.604 1132,1641.5 v2(1132,1640.75) ; 1132.3,1655.2 1132.3,1657.9 1136.453,1662.053 UT2.13@1136.453,1663.754
  BottomLayer w0.2: v2(1132,1640.75) 1132,1639.5 1137.25,1634.25 J4.21@1156.5,1634.25 ; 1155.088,1634.25 ccw(c1155.088,1635.712) J4.21@1156.122,1634.678 ; 1155.329,1634.25 cw(c1155.329,1633.129) J4.21@1156.122,1633.922 ; 1155.57,1634.25 ccw(c1155.57,1635.23) J4.21@1156.263,1634.537 ; 1155.812,1634.25 cw(c1155.812,1633.612) J4.21@1156.263,1634.063
XM0DATA5: J1.175 J4.22 UT2.12 | length 61.8
  TopLayer w0.135: 1131.497,1646.803 1131.497,1650.897 1131.896,1651.296 J1.175@1131.896,1653.706
  TopLayer w0.2: v2(1131.25,1640) 1131.25,1641.75 1131.496,1641.996 1131.496,1642.596 ; 1131.5,1642.6 1131.5,1646.8 ; J1.175@1131.896,1653.706 1131.9,1653.71 1131.9,1663.6 1133.804,1665.504 UT2.12@1134.703,1665.504
  BottomLayer w0.2: v2(1131.25,1640) 1131.25,1639 1136.5,1633.75 1146,1633.75 1146.45,1633.3 1157.5,1633.3 J4.22@1158.5,1634.3 ; J4.22@1157.965,1634.3 cw(c1156.673,1634.3) 1157.587,1633.387 cw(c1158.5,1632.473) J4.22@1158.5,1633.765 ; J4.22@1158.165,1634.3 cw(c1157.356,1634.3) 1157.928,1633.728 cw(c1158.5,1633.156) J4.22@1158.5,1633.965
XM0DATA6: J1.174 J4.23 UT2.11 | length 64.2
  TopLayer w0.135: J1.174@1131.096,1648.506 1131.096,1650.9 1131.497,1651.302 1131.497,1655.197
  TopLayer w0.2: v2(1130.5,1640.75) 1130.5,1641.75 1131.096,1642.346 J1.174@1131.096,1648.506 ; 1131.5,1655.2 1131.5,1663.8 1133.704,1666.004 UT2.11@1134.703,1666.004
  BottomLayer w0.2: v2(1130.5,1640.75) 1130.5,1639.1 1143.441,1626.159 1152.068,1626.159 1152.494,1626.585 1152.494,1628.591 1156.233,1632.331 J4.23@1156.335,1632.331
XM0DATA7: J1.173 J4.24 UT2.10 | length 71.6
  TopLayer w0.135: 1130.695,1646.805 1130.695,1650.895 1131.096,1651.296 J1.173@1131.096,1653.706
  TopLayer w0.2: v2(1129.75,1640) 1129.75,1641.754 1130.696,1642.7 1130.7,1642.7 1130.7,1646.8 ; J1.173@1131.096,1653.706 1131.096,1663.996 1133.604,1666.504 UT2.10@1134.703,1666.504
  BottomLayer w0.2: v2(1129.75,1640) 1129.75,1639.15 1143.2,1625.7 1152.194,1625.7 1152.894,1626.4 1152.894,1628.392 1155.802,1631.3 1157.5,1631.3 J4.24@1158.5,1632.3 ; J4.24@1157.965,1632.3 cw(c1156.673,1632.3) 1157.587,1631.387 cw(c1158.5,1630.473) J4.24@1158.5,1631.765 ; J4.24@1158.165,1632.3 cw(c1157.356,1632.3) 1157.928,1631.728 cw(c1158.5,1631.156) J4.24@1158.5,1631.965
XM0DATA8: J1.188 J4.9 UT2.31 | length 54.5
  TopLayer w0.135: J1.188@1136.696,1648.506 1136.696,1650.896 1137.094,1651.294 1137.094,1655.194
  TopLayer w0.2: J1.188@1136.66,1647.307 1136.66,1647.09 1137.271,1646.479 v2(1137.59,1646.479) ; J1.188@1136.696,1647.307 J1.188@1136.696,1648.506 ; 1137.1,1655.2 1137.1,1655.74 1139.66,1658.3 1142.3,1658.3 1146.6,1662.6 1146.6,1666.5 1144.596,1668.504 UT2.31@1143.703,1668.504
  BottomLayer w0.2: v2(1137.59,1646.479) 1139.479,1646.479 1141.5,1648.5 1145.75,1648.5 1148.127,1646.123 J4.9@1156.487,1646.123 ; 1154.782,1646.123 ccw(c1154.782,1648.018) J4.9@1156.122,1646.678 ; 1155.264,1646.123 ccw(c1155.264,1647.536) J4.9@1156.263,1646.537 ; 1155.635,1646.123 cw(c1155.635,1645.435) J4.9@1156.122,1645.922 ; 1155.747,1646.123 ccw(c1155.747,1647.053) J4.9@1156.405,1646.395
XM0DATA9: J1.187 J4.10 UT2.29 | length 56.7
  TopLayer w0.135: 1136.296,1646.804 1136.296,1650.905 1136.696,1651.304 J1.187@1136.696,1653.706
  TopLayer w0.2: 1136.3,1646.8 1136.3,1646.27 v2(1136.802,1645.768) ; J1.187@1136.7,1653.71 1136.7,1655.906 1139.494,1658.7 1142.1,1658.7 1146.2,1662.8 1146.2,1666.2 1144.896,1667.504 UT2.29@1143.703,1667.504
  BottomLayer w0.2: v2(1136.802,1645.768) 1139.518,1645.768 1141.75,1648 1145.5,1648 1148.2,1645.3 1157.4,1645.3 J4.10@1158.4,1646.3 ; 1157.416,1645.316 cw(c1158.5,1644.232) J4.10@1158.5,1645.765 ; 1157.657,1645.557 ccw(c1156.915,1646.3) J4.10@1157.965,1646.3 ; 1157.757,1645.657 cw(c1158.5,1644.915) J4.10@1158.5,1645.965 ; 1157.999,1645.899 ccw(c1157.598,1646.3) J4.10@1158.165,1646.3
XM0DATA10: J1.186 J4.11 UT2.28 | length 55
  TopLayer w0.135: J1.186@1135.896,1648.506 1135.896,1650.896 1136.296,1651.296 1136.296,1655.196
  TopLayer w0.2: J1.186@1135.896,1648.506 1135.896,1645.604 1136.5,1645 v2(1137.6,1645) ; 1136.3,1655.2 1136.3,1656.072 1139.328,1659.1 1141.934,1659.1 1145.8,1662.966 1145.8,1666 1144.8,1667 UT2.28@1143.8,1667
  BottomLayer w0.2: v2(1137.6,1645) 1139.5,1645 1142,1647.5 1145.25,1647.5 1148.5,1644.25 J4.11@1156.25,1644.25 ; 1155.088,1644.25 ccw(c1155.088,1645.712) J4.11@1156.122,1644.678 ; 1155.329,1644.25 cw(c1155.329,1643.129) J4.11@1156.122,1643.922 ; 1155.57,1644.25 ccw(c1155.57,1645.23) J4.11@1156.263,1644.537 ; 1155.812,1644.25 cw(c1155.812,1643.612) J4.11@1156.263,1644.063 ; J4.11@1156.25,1644.3 J4.11@1156.5,1644.3
XM0DATA11: J1.185 J4.12 UT2.27 | length 58.2
  TopLayer w0.135: 1135.497,1646.797 1135.497,1650.897 1135.896,1651.296 J1.185@1135.896,1653.706
  TopLayer w0.2: 1135.496,1646.796 1135.496,1644.754 1136,1644.25 v2@1136.75,1644.25 ; J1.185@1135.9,1653.71 1135.9,1656.237 1139.163,1659.5 1141.769,1659.5 1145.4,1663.131 1145.4,1665.8 1144.696,1666.504 UT2.27@1143.703,1666.504
  BottomLayer w0.2: v2(1136.802,1644.294) 1139.544,1644.294 1142.25,1647 1145,1647 1148.7,1643.3 1157.5,1643.3 J4.12@1158.5,1644.3 ; J4.12@1157.965,1644.3 cw(c1156.673,1644.3) 1157.587,1643.387 cw(c1158.5,1642.473) J4.12@1158.5,1643.765 ; J4.12@1158.165,1644.3 cw(c1157.356,1644.3) 1157.928,1643.728 cw(c1158.5,1643.156) J4.12@1158.5,1643.965
XM0DATA12: J1.184 J4.13 UT2.26 | length 56.4
  TopLayer w0.135: J1.184@1135.096,1648.506 1135.096,1650.896 1135.497,1651.297 1135.497,1655.197
  TopLayer w0.2: J1.184@1135.096,1648.506 1135.096,1644.154 1135.743,1643.507 v2@1137.5,1643.507 ; 1135.5,1655.2 1135.5,1656.403 1138.997,1659.9 1141.603,1659.9 1145,1663.297 1145,1665.6 1144.596,1666.004 UT2.26@1143.703,1666.004
  BottomLayer w0.2: v2(1137.59,1643.507) 1139.507,1643.507 1142.5,1646.5 1144.75,1646.5 1149,1642.25 J4.13@1156.5,1642.25 ; 1155.088,1642.25 ccw(c1155.088,1643.712) J4.13@1156.122,1642.678 ; 1155.329,1642.25 cw(c1155.329,1641.129) J4.13@1156.122,1641.922 ; 1155.571,1642.25 ccw(c1155.571,1643.229) J4.13@1156.263,1642.537 ; 1155.812,1642.25 cw(c1155.812,1641.612) J4.13@1156.263,1642.063
XM0DATA13: J1.183 J4.14 UT2.25 | length 56.6
  TopLayer w0.135: 1134.695,1646.805 1134.695,1650.895 1135.096,1651.296 J1.183@1135.096,1653.706
  TopLayer w0.2: 1134.7,1646.8 1134.696,1646.804 1134.696,1643.87 1135.77,1642.796 v2(1136.802,1642.796) ; J1.183@1135.1,1653.71 1135.1,1656.569 1138.831,1660.3 ; 1138.9,1660.3 1141.437,1660.3 1144.6,1663.463 1144.6,1665.3 1144.396,1665.504 UT2.25@1143.703,1665.504 ; UT2.25@1144.303,1665.454 cw(c1144.303,1665.11) 1144.547,1665.353
  BottomLayer w0.2: v2(1136.802,1642.796) 1141.954,1642.796 1143.45,1641.3 1157.55,1641.3 J4.14@1158.424,1642.174 ; 1157.575,1641.325 ccw(c1156.633,1642.267) J4.14@1157.965,1642.291 ; 1157.672,1641.422 cw(c1158.5,1640.594) J4.14@1158.5,1641.765 ; 1157.908,1641.658 ccw(c1157.288,1642.279) J4.14@1158.165,1642.294 ; 1158.013,1641.763 cw(c1158.5,1641.277) J4.14@1158.5,1641.965
XM0DATA14: J1.182 J4.15 UT2.24 | length 51.5
  TopLayer w0.135: J1.182@1134.296,1648.506 1134.296,1650.896 1134.695,1651.295 1134.695,1655.195
  TopLayer w0.2: J1.182@1134.296,1648.506 1134.296,1643.704 1135.941,1642.059 v2(1137.615,1642.059) ; 1134.7,1655.2 1134.7,1656.734 1138.666,1660.7 1140.8,1660.7 1141.953,1661.853 UT2.24@1141.953,1663.754
  BottomLayer w0.2: v2@1137.514,1642.034 1142.035,1642.034 1143.769,1640.3 J4.15@1156.5,1640.3 ; J4.15@1156.122,1639.922 ccw(c1155.208,1639.008) 1155.208,1640.3 ccw(c1155.208,1641.592) J4.15@1156.122,1640.678 ; J4.15@1156.263,1640.063 ccw(c1155.691,1639.491) 1155.691,1640.3 ccw(c1155.691,1641.109) J4.15@1156.263,1640.537
XM0DATA15: J1.181 J4.16 UT2.22 | length 54.5
  TopLayer w0.135: 1133.896,1646.804 1133.896,1650.896 1134.296,1651.296 J1.181@1134.296,1653.706
  TopLayer w0.2: 1133.9,1646.8 1133.896,1646.796 1133.896,1643.354 1135.953,1641.297 v2(1136.802,1641.297) ; J1.181@1134.296,1653.706 1134.296,1656.454 ; 1134.3,1656.304 1134.3,1656.9 1138.5,1661.1 1140.2,1661.1 1140.953,1661.853 UT2.22@1140.953,1663.754
  BottomLayer w0.2: v2(1136.802,1641.297) 1138.953,1641.297 1140.95,1639.3 1157.5,1639.3 1158.4,1640.2 J4.16@1158.5,1640.3 ; 1157.928,1639.728 ccw(c1157.356,1640.3) J4.16@1158.165,1640.3 ; 1157.928,1639.728 cw(c1158.5,1639.156) J4.16@1158.5,1639.965 ; J4.16@1157.965,1640.3 cw(c1156.673,1640.3) 1157.587,1639.387 cw(c1158.5,1638.473) J4.16@1158.5,1639.765
XM0DATA_RDN: J1.192
XM0OEN: J1.194 J4.7 UT2.35 | length 57.5
  TopLayer w0.135: 1137.896,1655.196 1137.896,1651.504 1139.096,1650.304 J1.194@1139.096,1648.506
  TopLayer w0.2: 1137.9,1655.2 1137.9,1655.975 1139.825,1657.9 1142.5,1657.9 1147.6,1663 1147.6,1670.2 1147.296,1670.504 UT2.35@1143.703,1670.504 ; J1.194@1139.096,1648.506 1139.096,1646.243 1139.825,1645.514 1142.187,1645.514 1145.235,1648.562 1156.188,1648.562 J4.7@1156.5,1648.25 ; 1154.577,1648.562 cw(c1154.577,1646.377) J4.7@1156.122,1647.922 ; 1155.06,1648.562 cw(c1155.06,1646.86) J4.7@1156.263,1648.063 ; 1155.543,1648.562 cw(c1155.543,1647.343) J4.7@1156.405,1648.205 ; 1155.84,1648.562 ccw(c1155.84,1648.96) J4.7@1156.122,1648.678
XM0WAITN: J1.191 J4.8 | length 32.1
  TopLayer w0.135: J1.191@1138.296,1653.706 1138.296,1651.604 1139.497,1650.403 1139.497,1646.906
  TopLayer w0.2: 1139.5,1646.9 1139.496,1646.904 1139.496,1646.427 1140.003,1645.92 1141.984,1645.92 1145.314,1649.25 1157.55,1649.25 J4.8@1158.5,1648.3 ; J4.8@1157.965,1648.3 ccw(c1156.673,1648.3) 1157.587,1649.213 ccw(c1158.5,1650.127) J4.8@1158.5,1648.835 ; J4.8@1158.165,1648.3 ccw(c1157.356,1648.3) 1157.928,1648.872 ccw(c1158.5,1649.444) J4.8@1158.5,1648.635
XM0WEN: J1.193 J4.6 UT2.36 | length 59.2
  TopLayer w0.12: J1.193@1139.096,1653.706 J1.193@1139.096,1653.706
  TopLayer w0.135: J1.193@1139.096,1653.706 1139.096,1651.744 1140.296,1650.544 1140.296,1646.954
  TopLayer w0.2: J1.193@1139.096,1653.706 1139.096,1655.859 1139.1,1655.863 1139.1,1656.043 1140.157,1657.1 1142.9,1657.1 1148.4,1662.6 1148.4,1670.6 1147,1672 1145.6,1672 1144.604,1671.004 UT2.36@1143.703,1671.004 ; 1140.3,1647 1140.3,1646.95 1140.5,1646.75 1141.62,1646.75 1146.12,1651.25 1157.55,1651.25 J4.6@1158.5,1650.3 ; J4.6@1157.965,1650.3 ccw(c1156.673,1650.3) 1157.587,1651.213 ccw(c1158.5,1652.127) J4.6@1158.5,1650.835 ; J4.6@1158.165,1650.3 ccw(c1157.356,1650.3) 1157.928,1650.872 ccw(c1158.5,1651.444) J4.6@1158.5,1650.635
XMMC0CDN: J1.253 RS16.2 | length 49.4
  TopLayer w0.2: J1.253@1143.715,1617.595 1147.951,1617.595 1154.845,1610.7 1181.8,1610.7 1186,1606.5 RS16.2@1186.25,1606.5 ; 1185.176,1607.324 ccw(c1186.2,1608.349) RS16.2@1186.2,1606.9 ; 1185.517,1606.983 ccw(c1186.2,1607.666) RS16.2@1186.2,1606.7 ; 1185.659,1606.841 cw(c1185.317,1606.5) RS16.2@1185.8,1606.5
XMMC0CLK: J1.254 RS11.1 | length 59
  TopLayer w0.135: J1.254@1138.515,1617.595 1140.785,1617.595 1141.185,1617.194 1145.605,1617.194 ; J1.254@1139.658,1617.501 cw(c1139.884,1617.275) 1139.884,1617.595 cw(c1139.884,1617.914) J1.254@1139.658,1617.688
  TopLayer w0.2: 1145.605,1617.195 1147.773,1617.195 1154.668,1610.3 1181.634,1610.3 1184.605,1607.329 1184.605,1603.502 1186.107,1602 RS11.1@1186.25,1602 ; 1185.359,1602.748 ccw(c1186.2,1603.59) RS11.1@1186.2,1602.4 ; 1185.583,1602.524 cw(c1185.058,1602) RS11.1@1185.8,1602 ; RS11.1@1185.7,1602.407 ccw(c1186.2,1602.907) RS11.1@1186.2,1602.2
XMMC0CMD: J1.252 RS12.1 | length 53.5
  TopLayer w0.135: J1.252@1138.515,1618.395 1140.87,1618.395 1141.271,1617.994 1145.605,1617.994 ; J1.252@1139.658,1618.301 cw(c1139.884,1618.075) 1139.884,1618.395 cw(c1139.884,1618.714) J1.252@1139.658,1618.488
  TopLayer w0.2: 1145.605,1617.995 1148.116,1617.995 1155.011,1611.1 1186.15,1611.1 RS12.1@1186.25,1611 ; 1184.993,1611.1 cw(c1184.993,1609.793) RS12.1@1185.917,1610.717 ; RS12.1@1185.917,1611.283 cw(c1185.476,1611.724) 1185.476,1611.1 cw(c1185.476,1610.276) RS12.1@1186.059,1610.859
XMMC0DATA0: J1.255 RS10.1 | length 57.3
  TopLayer w0.2: J1.255@1143.715,1616.795 1147.608,1616.795 1154.502,1609.9 1181.469,1609.9 1184.069,1607.3 1184.069,1599.459 1186.028,1597.5 RS10.1@1186.25,1597.5 ; 1185.223,1598.305 ccw(c1186.2,1599.282) RS10.1@1186.2,1597.9 ; 1185.564,1597.963 ccw(c1186.2,1598.599) RS10.1@1186.2,1597.7 ; 1185.639,1597.889 cw(c1185.251,1597.5) RS10.1@1185.8,1597.5
XMMC0DATA1: J1.256 RS9.1 | length 64
  TopLayer w0.135: J1.256@1138.515,1616.795 1140.978,1616.795 1141.377,1616.395 1145.595,1616.395 ; J1.256@1139.658,1616.701 cw(c1139.884,1616.475) 1139.884,1616.795 cw(c1139.884,1617.114) J1.256@1139.658,1616.888
  TopLayer w0.2: 1145.6,1616.4 1145.605,1616.395 1147.442,1616.395 1154.336,1609.5 1181.303,1609.5 1183.669,1607.134 1183.669,1598.435 1186.104,1596 RS9.1@1186.25,1596 ; 1185.353,1596.751 ccw(c1186.2,1597.598) RS9.1@1186.2,1596.4 ; 1185.585,1596.519 cw(c1185.067,1596) RS9.1@1185.8,1596 ; 1185.694,1596.409 ccw(c1186.2,1596.915) RS9.1@1186.2,1596.2
XMMC0DATA2: J1.250 RS14.1 | length 58.2
  TopLayer w0.135: J1.250@1138.515,1619.195 1140.817,1619.195 1141.216,1618.795 1145.605,1618.795 ; J1.250@1139.658,1619.101 cw(c1139.884,1618.875) 1139.884,1619.195 cw(c1139.884,1619.514) J1.250@1139.658,1619.288
  TopLayer w0.2: 1145.605,1618.795 1148.455,1618.795 1155.35,1611.9 1183.9,1611.9 1184.8,1612.8 1184.8,1615.9 1185.9,1617 RS14.1@1186.25,1617 ; 1185.005,1616.105 cw(c1186.2,1614.91) RS14.1@1186.2,1616.6 ; 1185.346,1616.446 cw(c1186.2,1615.593) RS14.1@1186.2,1616.8 ; 1185.688,1616.788 cw(c1186.2,1616.276) RS14.1@1186.2,1617 ; RS14.1@1185.729,1616.829 ccw(c1185.559,1617) RS14.1@1185.8,1617
XMMC0DATA3: J1.251 RS13.1 | length 48.8
  TopLayer w0.2: J1.251@1143.715,1618.395 1148.29,1618.395 1155.184,1611.5 1184.9,1611.5 1185.9,1612.5 RS13.1@1186.25,1612.5 ; 1185.005,1611.605 cw(c1186.2,1610.41) RS13.1@1186.2,1612.1 ; 1185.346,1611.946 cw(c1186.2,1611.093) RS13.1@1186.2,1612.3 ; 1185.688,1612.288 cw(c1186.2,1611.776) RS13.1@1186.2,1612.5 ; RS13.1@1185.729,1612.329 ccw(c1185.559,1612.5) RS13.1@1185.8,1612.5
XMMC1CDN: J1.261 RD7.2 TF.1 | length 97.1
  TopLayer w0.2: J1.261@1143.715,1614.395 1146.484,1614.395 1169.678,1591.2 1176.4,1591.2 1184.7,1582.9 1203.35,1582.9 v2(1204.5,1581.75) ; TF.1@1210,1578.465 cw(c1210,1577.173) 1210.913,1578.087 cw(c1211.827,1579) TF.1@1210.535,1579 ; TF.1@1210,1578.665 cw(c1210,1577.856) 1210.572,1578.428 cw(c1211.144,1579) TF.1@1210.335,1579 ; TF.1@1210,1579 1211.25,1577.75 1211.25,1575.25 RD7.2@1213.5,1573 ; 1212.746,1573.754 cw(c1211.893,1572.9) RD7.2@1213.1,1572.9 ; 1212.988,1573.512 ccw(c1213.5,1574.024) RD7.2@1213.5,1573.3 ; 1213.088,1573.412 cw(c1212.576,1572.9) RD7.2@1213.3,1572.9
  BottomLayer w0.2: v2(1204.5,1581.75) 1207.25,1581.75 TF.1@1210,1579 ; TF.1@1209.465,1579 ccw(c1208.173,1579) 1209.087,1579.913 ccw(c1210,1580.827) TF.1@1210,1579.535 ; TF.1@1209.665,1579 ccw(c1208.856,1579) 1209.428,1579.572 ccw(c1210,1580.144) TF.1@1210,1579.335
XMMC1CLK: CS2.1 J1.262 RD3.2 TF.7 | length 104.1
  TopLayer w0.135: J1.262@1138.515,1614.395 1141.488,1614.395 1141.886,1613.996 1145.196,1613.996 ; J1.262@1139.658,1614.301 cw(c1139.884,1614.075) 1139.884,1614.395 cw(c1139.884,1614.714) J1.262@1139.658,1614.488
  TopLayer w0.2: 1145.2,1614 1146.294,1614 1146.294,1613.995 1169.489,1590.8 1176.2,1590.8 1184.5,1582.5 1202.5,1582.5 1204.011,1580.989 TF.7@1204.011,1578.989 1205,1578 1205,1576 1203.6,1574.6 RD3.2@1203.6,1572.85 ; RD3.2@1203.117,1573.183 ccw(c1201.951,1574.349) 1203.6,1574.349 ; RD3.2@1203.259,1573.041 ccw(c1202.434,1573.866) 1203.6,1573.866 ; RD3.2@1203.4,1572.9 ccw(c1202.917,1573.383) 1203.6,1573.383 ccw(c1203.883,1573.383) RD3.2@1203.683,1573.183 ; RD3.2@1203.541,1572.659 cw(c1203.928,1572.272) 1203.928,1572.819 ; RD3.2@1203.631,1572.819 CS2.1@1205.302,1572.819 ; TF.7@1203.633,1579.367 ccw(c1202.719,1580.28) 1204.011,1580.28 ccw(c1205.303,1580.28) TF.7@1204.389,1579.367 ; RD3.2@1203.683,1572.517 cw(c1204.411,1571.79) 1204.411,1572.819 ; RD3.2@1203.683,1573.083 ccw(c1204.321,1573.721) 1204.321,1572.819 ; TF.7@1203.774,1579.226 ccw(c1203.202,1579.798) 1204.011,1579.798 ccw(c1204.82,1579.798) TF.7@1204.248,1579.226 ; TF.7@1204.011,1578.454 cw(c1204.011,1577.162) 1204.924,1578.075 cw(c1205.838,1578.989) TF.7@1204.546,1578.989 ; TF.7@1204.011,1578.654 cw(c1204.011,1577.845) 1204.583,1578.417 cw(c1205.155,1578.989) TF.7@1204.346,1578.989 ; 1204.091,1572.819 ccw(c1204.091,1573.848) CS2.1@1204.819,1573.12 ; 1204.181,1572.819 cw(c1204.181,1571.916) CS2.1@1204.819,1572.554 ; 1204.574,1572.819 ccw(c1204.574,1573.365) CS2.1@1204.96,1572.979
XMMC1CMD: J1.260 RD4.2 TF.5 | length 99.7
  TopLayer w0.135: J1.260@1138.515,1615.195 1141.197,1615.195 1141.597,1614.795 1145.205,1614.795 ; J1.260@1139.658,1615.101 cw(c1139.884,1614.875) 1139.884,1615.195 cw(c1139.884,1615.514) J1.260@1139.658,1615.288
  TopLayer w0.2: 1145.205,1614.795 1146.668,1614.795 ; 1146.668,1614.776 1146.668,1614.795 ; TF.5@1205.633,1579.367 ccw(c1204.719,1580.28) 1206.011,1580.28 ccw(c1207.303,1580.28) TF.5@1206.389,1579.367 ; TF.5@1205.774,1579.226 ccw(c1205.202,1579.798) 1206.011,1579.798 ccw(c1206.82,1579.798) TF.5@1206.248,1579.226 ; TF.5@1206.011,1578.454 cw(c1206.011,1577.765) 1206.498,1578.252 ; TF.5@1206.144,1578.968 ccw(c1206.759,1578.871) 1206.319,1578.431 ; TF.5@1206.342,1578.937 ccw(c1207.24,1578.796) 1206.597,1578.153 ; TF.5@1206.54,1578.906 ccw(c1207.72,1578.72) 1206.875,1577.875 ; RD4.2@1208.417,1573.183 ccw(c1207.734,1573.866) 1208.7,1573.866 ccw(c1209.666,1573.866) RD4.2@1208.983,1573.183 ; RD4.2@1208.7,1572.85 1208.7,1574.05 1207,1575.75 1207,1577.75 1206.011,1578.739 1206.011,1581.489 1204.2,1583.3 1184.9,1583.3 1176.6,1591.6 1169.863,1591.6 1146.668,1614.795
